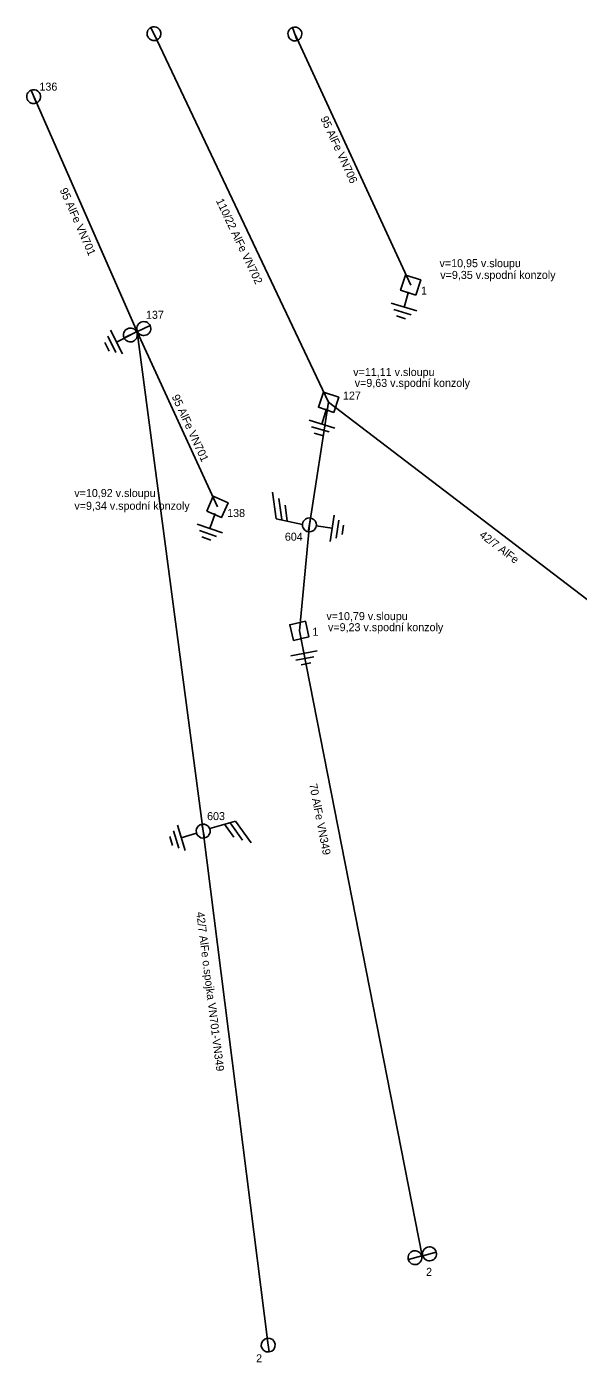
# Model space of a CAD drawing. Extents: x -536386 to -535479, y -1201638 to -1200910.
# Drawn here: x -536255.4 to -536203.8, y -1201365.1 to -1201240 of the extents above; entities that cross this region are included whole.
import ezdxf

# ---------------------------------------------------------------- set-up
doc = ezdxf.new("R2010")
doc.units = 0
for name, color, linetype in [('DOPLŇ_POPISY', 7, 'Continuous'), ('ELE_EON', 7, 'Continuous'), ('ELE_EON_POPIS', 7, 'Continuous')]:
    doc.layers.add(name, color=color, linetype=linetype)

msp = doc.modelspace()

# ---------------------------------------------------------------- linework, layer by layer
at = {"layer": 'ELE_EON'}
for p, q in [((-536243.19, -1201241.21), (-536243.75, -1201240.03)), ((-536230.06, -1201241.26), (-536230.5, -1201240.04)), ((-536243.47, -1201240.62), (-536227.12, -1201275.16)), ((-536230.28, -1201240.65), (-536219.44, -1201264.18)), ((-536254.48, -1201247.12), (-536254.98, -1201245.92)), ((-536254.73, -1201246.52), (-536245.05, -1201268.55)), ((-536220.06, -1201266.24), (-536219.63, -1201264.8)), ((-536221.26, -1201265.88), (-536218.87, -1201266.6)), ((-536221.02, -1201266.47), (-536219.39, -1201266.96)), ((-536220.78, -1201267.07), (-536219.92, -1201267.33)), ((-536247.53, -1201268.4), (-536246.41, -1201270.63)), ((-536246.97, -1201269.52), (-536245.63, -1201268.84)), ((-536245.1, -1201268.57), (-536246.27, -1201269.13)), ((-536245.05, -1201268.55), (-536237.53, -1201284.96)), ((-536243.83, -1201267.97), (-536245, -1201268.53)), ((-536248.07, -1201269.56), (-536247.66, -1201270.37)), ((-536247.8, -1201268.98), (-536247.04, -1201270.5)), ((-536227.75, -1201277.22), (-536227.31, -1201275.78)), ((-536228.94, -1201276.85), (-536226.55, -1201277.58)), ((-536228.71, -1201277.45), (-536227.08, -1201277.94)), ((-536228.47, -1201278.04), (-536227.61, -1201278.3)), ((-536232.03, -1201286.07), (-536232.37, -1201283.59)), ((-536231.51, -1201286.15), (-536231.79, -1201284.17)), ((-536230.99, -1201286.28), (-536231.2, -1201284.79)), ((-536238.25, -1201286.99), (-536237.75, -1201285.57)), ((-536229.58, -1201286.6), (-536232.03, -1201286.07)), ((-536228.81, -1201286.01), (-536229.03, -1201287.29)), ((-536226.97, -1201288.2), (-536226.61, -1201285.73)), ((-536226.42, -1201287.88), (-536226.17, -1201286.19)), ((-536239.43, -1201286.57), (-536237.07, -1201287.4)), ((-536239.22, -1201287.17), (-536237.61, -1201287.74)), ((-536226.79, -1201286.96), (-536228.28, -1201286.74)), ((-536225.87, -1201287.55), (-536225.74, -1201286.66)), ((-536239, -1201287.78), (-536238.16, -1201288.08)), ((-536229.44, -1201298.68), (-536229.73, -1201297.21)), ((-536230.67, -1201298.92), (-536228.21, -1201298.44)), ((-536230.18, -1201299.33), (-536228.51, -1201299)), ((-536229.69, -1201299.75), (-536228.8, -1201299.57)), ((-536241.28, -1201314.78), (-536240.55, -1201317.17)), ((-536238.74, -1201315.98), (-536238.98, -1201314.7)), ((-536238.25, -1201315.08), (-536235.84, -1201314.41)), ((-536236.86, -1201314.7), (-536235.98, -1201315.92)), ((-536236.33, -1201314.57), (-536235.17, -1201316.2)), ((-536235.84, -1201314.41), (-536234.38, -1201316.44)), ((-536242, -1201315.84), (-536241.74, -1201316.7)), ((-536241.64, -1201315.31), (-536241.14, -1201316.93)), ((-536240.91, -1201315.97), (-536239.48, -1201315.53)), ((-536218.41, -1201355.14), (-536219.66, -1201355.48)), ((-536217.06, -1201354.78), (-536218.31, -1201355.12)), ((-536232.7, -1201364.14), (-536232.86, -1201362.86))]:
    msp.add_line(p, q, dxfattribs=at)
for points in [[(-536218.95, -1201265.12), (-536218.5, -1201263.69), (-536219.93, -1201263.24), (-536220.38, -1201264.67)], [(-536226.65, -1201276.11), (-536226.17, -1201274.69), (-536227.59, -1201274.21), (-536228.07, -1201275.63)], [(-536238.52, -1201285.35), (-536237.14, -1201285.95), (-536236.54, -1201284.57), (-536237.92, -1201283.97)], [(-536230.42, -1201297.47), (-536228.96, -1201297.13), (-536229.3, -1201295.67), (-536230.76, -1201296.01)]]:
    msp.add_lwpolyline(points, close=True, dxfattribs=at)
for points in [[(-536245.05, -1201268.55), (-536238.86, -1201315.34), (-536232.78, -1201363.5)], [(-536227.12, -1201275.16), (-536228.92, -1201286.65), (-536229.86, -1201296.57), (-536218.36, -1201355.13)], [(-536227.12, -1201275.16), (-536199.36, -1201296.36), (-536187.58, -1201305.35), (-536147.73, -1201309.76)]]:
    msp.add_lwpolyline(points, dxfattribs=at)
for centre, start, end in [((-536243.47, -1201240.62), 115.7475, 295.7475), ((-536243.47, -1201240.62), 295.7475, 115.7475), ((-536230.28, -1201240.65), 109.9449, 289.9449), ((-536230.28, -1201240.65), 289.9449, 109.9449), ((-536254.73, -1201246.52), 112.3323, 292.3323), ((-536254.73, -1201246.52), 292.3323, 112.3323), ((-536244.42, -1201268.25), 25.4764, 205.4764), ((-536245.68, -1201268.85), 25.4764, 205.4764), ((-536245.68, -1201268.85), 205.4764, 25.4764), ((-536244.42, -1201268.25), 205.4764, 25.4764), ((-536228.92, -1201286.65), 80.3914, 260.3914), ((-536228.92, -1201286.65), 260.3914, 80.3914), ((-536238.86, -1201315.34), 101.0368, 281.0368), ((-536238.86, -1201315.34), 281.0368, 101.0368), ((-536219.04, -1201355.31), 14.8987, 194.8987), ((-536219.04, -1201355.31), 194.8987, 14.8987), ((-536217.68, -1201354.95), 14.8987, 194.8987), ((-536217.68, -1201354.95), 194.8987, 14.8987), ((-536232.78, -1201363.5), 97.4314, 277.4314), ((-536232.78, -1201363.5), 277.4314, 97.4314)]:
    msp.add_arc(centre, 0.65, start, end, dxfattribs=at)

# ---------------------------------------------------------------- texts
at = {"layer": 'DOPLŇ_POPISY'}
for s, p in [('v=10,95 v.sloupu', (-536216.74, -1201262.5)), ('v=9,35 v.spodní konzoly', (-536216.67, -1201263.6)), ('v=11,11 v.sloupu', (-536224.82, -1201272.7)), ('v=9,63 v.spodní konzoly', (-536224.68, -1201273.72)), ('v=10,92 v.sloupu', (-536250.93, -1201284.04)), ('v=9,34 v.spodní konzoly', (-536250.92, -1201285.23)), ('v=10,79 v.sloupu', (-536227.33, -1201295.57)), ('v=9,23 v.spodní konzoly', (-536227.18, -1201296.61))]:
    msp.add_text(s, height=0.75, dxfattribs=at).set_placement(p)
at = {"layer": 'ELE_EON_POPIS'}
for s, p in [('136', (-536254.19, -1201245.96)), ('1', (-536218.47, -1201265.07)), ('137', (-536244.22, -1201267.34)), ('127', (-536225.78, -1201274.91)), ('138', (-536236.62, -1201285.91)), ('604', (-536231.22, -1201288.13)), ('1', (-536228.64, -1201297.04)), ('603', (-536238.5, -1201314.31)), ('2', (-536218, -1201357.01)), ('2', (-536233.91, -1201365.11))]:
    msp.add_text(s, height=0.75, dxfattribs=at).set_placement(p)
for s, rotation, p in [('95 AlFe VN706', 294.735, (-536227.91, -1201248.56)), ('95 AlFe VN701', 293.7207, (-536252.31, -1201255.27)), ('110/22 AlFe VN702', 295.3312, (-536237.69, -1201256.27)), ('95 AlFe VN701', 294.62, (-536241.83, -1201274.63)), ('42/7 AlFe', 322.6314, (-536213.08, -1201287.72)), ('70 AlFe VN349', 281.1103, (-536228.95, -1201310.96)), ('42/7 AlFe o.spojka VN701-VN349', 277.1953, (-536239.51, -1201322.95))]:
    msp.add_text(s, height=0.75, rotation=rotation, dxfattribs=at).set_placement(p)

doc.saveas('drawing.dxf')
